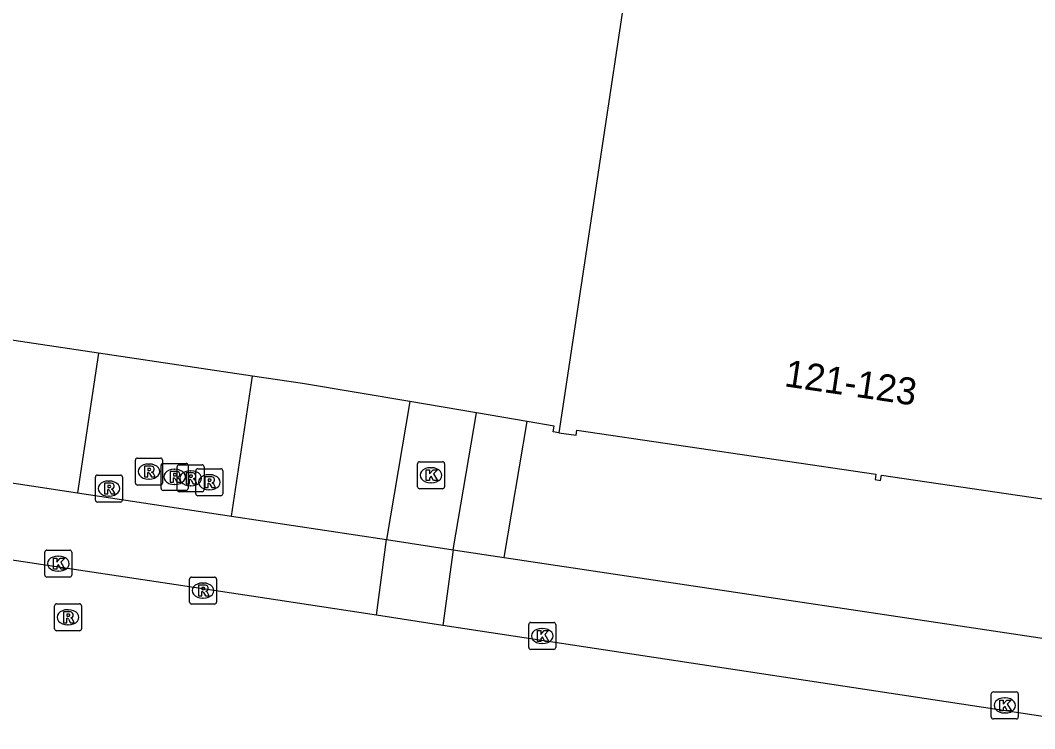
# Model space of a CAD drawing. Extents: x 163010 to 163853, y 382793 to 383982.
# Drawn here: x 163603.4 to 163641, y 382812.73 to 382838.98 of the extents above; entities that cross this region are included whole.
import ezdxf

# ---------------------------------------------------------------- set-up
doc = ezdxf.new("R2010")
doc.units = 0
for name, color, linetype in [('IMGEO_Kolk', 7, 'Continuous'), ('IMGEO_Pand', 7, 'Continuous'), ('IMGEO_Pand_nummerreeks', 7, 'Continuous'), ('IMGEO_Parkeervlak_open', 7, 'Continuous'), ('IMGEO_Rijbaan_lokaal_open', 7, 'Continuous'), ('IMGEO_Rioolput', 7, 'Continuous'), ('IMGEO_Voetpad_open', 7, 'Continuous')]:
    doc.layers.add(name, color=color, linetype=linetype)

msp = doc.modelspace()

# ---------------------------------------------------------------- linework, layer by layer
at = {"layer": 'IMGEO_Kolk'}
for p, q in [((163618.126, 382821.699), (163618.126, 382822.551)), ((163618.201, 382822.625), (163619.053, 382822.625)), ((163618.614, 382822.405), (163618.639, 382822.405)), ((163619.127, 382822.551), (163619.127, 382821.699)), ((163618.637, 382821.845), (163618.612, 382821.845)), ((163619.053, 382821.625), (163618.201, 382821.625)), ((163604.309, 382818.423), (163604.309, 382819.275)), ((163604.384, 382819.349), (163605.236, 382819.349)), ((163604.797, 382819.129), (163604.822, 382819.129)), ((163605.31, 382819.275), (163605.31, 382818.423)), ((163605.236, 382818.349), (163604.384, 382818.349)), ((163604.82, 382818.569), (163604.795, 382818.569)), ((163622.248, 382815.742), (163622.248, 382816.594)), ((163622.323, 382816.668), (163623.175, 382816.668)), ((163622.736, 382816.448), (163622.761, 382816.448)), ((163623.249, 382816.594), (163623.249, 382815.742)), ((163623.175, 382815.668), (163622.323, 382815.668)), ((163622.759, 382815.888), (163622.734, 382815.888)), ((163639.395, 382813.168), (163639.395, 382814.02)), ((163639.47, 382814.094), (163640.322, 382814.094)), ((163639.883, 382813.874), (163639.908, 382813.874)), ((163640.396, 382814.02), (163640.396, 382813.168)), ((163640.322, 382813.094), (163639.47, 382813.094)), ((163639.906, 382813.314), (163639.881, 382813.314))]:
    msp.add_line(p, q, dxfattribs=at)
for points in [[(163618.126, 382821.699), (163618.126, 382822.551)], [(163618.201, 382822.625), (163619.053, 382822.625)], [(163619.127, 382822.551), (163619.127, 382821.699)], [(163618.447, 382822.325), (163618.57, 382822.325), (163618.57, 382822.174), (163618.7, 382822.325), (163618.864, 382822.325), (163618.718, 382822.174), (163618.871, 382821.925), (163618.719, 382821.925), (163618.634, 382822.089), (163618.57, 382822.022), (163618.57, 382821.925), (163618.447, 382821.925), (163618.447, 382822.325)], [(163619.053, 382821.625), (163618.201, 382821.625)], [(163604.309, 382818.423), (163604.309, 382819.275)], [(163604.384, 382819.349), (163605.236, 382819.349)], [(163604.63, 382819.049), (163604.753, 382819.049), (163604.753, 382818.898), (163604.883, 382819.049), (163605.047, 382819.049), (163604.901, 382818.898), (163605.054, 382818.649), (163604.902, 382818.649), (163604.817, 382818.813), (163604.753, 382818.746), (163604.753, 382818.649), (163604.63, 382818.649), (163604.63, 382819.049)], [(163605.31, 382819.275), (163605.31, 382818.423)], [(163605.236, 382818.349), (163604.384, 382818.349)], [(163622.248, 382815.742), (163622.248, 382816.594)], [(163622.323, 382816.668), (163623.175, 382816.668)], [(163623.249, 382816.594), (163623.249, 382815.742)], [(163622.569, 382816.368), (163622.692, 382816.368), (163622.692, 382816.217), (163622.822, 382816.368), (163622.986, 382816.368), (163622.84, 382816.217), (163622.993, 382815.968), (163622.841, 382815.968), (163622.756, 382816.132), (163622.692, 382816.065), (163622.692, 382815.968), (163622.569, 382815.968), (163622.569, 382816.368)], [(163623.175, 382815.668), (163622.323, 382815.668)], [(163639.395, 382813.168), (163639.395, 382814.02)], [(163639.47, 382814.094), (163640.322, 382814.094)], [(163639.716, 382813.794), (163639.839, 382813.794), (163639.839, 382813.643), (163639.969, 382813.794), (163640.133, 382813.794), (163639.987, 382813.643), (163640.14, 382813.394), (163639.988, 382813.394), (163639.903, 382813.558), (163639.839, 382813.491), (163639.839, 382813.394), (163639.716, 382813.394), (163639.716, 382813.794)], [(163640.396, 382814.02), (163640.396, 382813.168)], [(163640.322, 382813.094), (163639.47, 382813.094)]]:
    msp.add_lwpolyline(points, dxfattribs=at)
for centre, start, end in [((163618.203, 382822.549), 91.552, 178.448), ((163618.203, 382822.549), 91.552, 178.448), ((163619.051, 382822.549), 1.552, 88.448), ((163619.051, 382822.549), 1.552, 88.448), ((163618.203, 382821.701), 181.552, 268.448), ((163618.203, 382821.701), 181.552, 268.448), ((163619.051, 382821.701), 271.552, 358.448), ((163619.051, 382821.701), 271.552, 358.448), ((163604.386, 382819.273), 91.552, 178.448), ((163604.386, 382819.273), 91.552, 178.448), ((163605.234, 382819.273), 1.552, 88.448), ((163605.234, 382819.273), 1.552, 88.448), ((163604.386, 382818.425), 181.552, 268.448), ((163604.386, 382818.425), 181.552, 268.448), ((163605.234, 382818.425), 271.552, 358.448), ((163605.234, 382818.425), 271.552, 358.448), ((163622.325, 382816.592), 91.552, 178.448), ((163622.325, 382816.592), 91.552, 178.448), ((163623.173, 382816.592), 1.552, 88.448), ((163623.173, 382816.592), 1.552, 88.448), ((163622.325, 382815.744), 181.552, 268.448), ((163622.325, 382815.744), 181.552, 268.448), ((163623.173, 382815.744), 271.552, 358.448), ((163623.173, 382815.744), 271.552, 358.448), ((163639.472, 382814.018), 91.552, 178.448), ((163639.472, 382814.018), 91.552, 178.448), ((163640.32, 382814.018), 1.552, 88.448), ((163640.32, 382814.018), 1.552, 88.448), ((163639.472, 382813.17), 181.552, 268.448), ((163639.472, 382813.17), 181.552, 268.448), ((163640.32, 382813.17), 271.552, 358.448), ((163640.32, 382813.17), 271.552, 358.448)]:
    msp.add_arc(centre, 0.0765, start, end, dxfattribs=at)
for centre, major_axis, ratio, start_param, end_param in [((163618.613, 382822.125), (-0.387, 0.002), 0.722429, 4.712389, 7.853982), ((163618.638, 382822.125), (-0.39, 0.002), 0.717154, 1.570796, 4.712389), ((163604.796, 382818.849), (-0.387, 0.002), 0.722429, 4.712389, 7.853982), ((163604.821, 382818.849), (-0.39, 0.002), 0.717154, 1.570796, 4.712389), ((163622.735, 382816.168), (-0.387, 0.002), 0.722429, 4.712389, 7.853982), ((163622.76, 382816.168), (-0.39, 0.002), 0.717154, 1.570796, 4.712389), ((163639.882, 382813.594), (-0.387, 0.002), 0.722429, 4.712389, 7.853982), ((163639.907, 382813.594), (-0.39, 0.002), 0.717154, 1.570796, 4.712389)]:
    msp.add_ellipse(centre, major_axis=major_axis, ratio=ratio, start_param=start_param, end_param=end_param, dxfattribs=at)
at = {"layer": 'IMGEO_Pand'}
for points in [[(163632.813, 382886.325), (163623.367, 382823.699)], [(163606.296, 382826.651), (163596.21, 382828.157)], [(163612.003, 382825.799), (163606.296, 382826.651)], [(163617.839, 382824.851), (163613.862, 382825.522), (163612.003, 382825.799)], [(163620.306, 382824.434), (163617.839, 382824.851)], [(163622.192, 382824.116), (163620.306, 382824.434)], [(163623.367, 382823.699), (163623.155, 382823.73), (163623.187, 382823.948), (163622.192, 382824.116)], [(163623.367, 382823.699), (163624.005, 382823.606), (163624.033, 382823.795), (163635.119, 382822.162), (163635.089, 382821.964), (163635.286, 382821.935), (163635.329, 382822.122), (163645.496, 382820.628)]]:
    msp.add_lwpolyline(points, dxfattribs=at)
at = {"layer": 'IMGEO_Parkeervlak_open'}
msp.add_lwpolyline([(163621.341, 382819.074), (163622.192, 382824.116)], dxfattribs=at)
at = {"layer": 'IMGEO_Rijbaan_lokaal_open'}
for points in [[(163616.599, 382816.941), (163611.973, 382817.64), (163603.009, 382818.995), (163595.965, 382820.06), (163595.022, 382820.202)], [(163619.059, 382816.555), (163616.599, 382816.941)], [(163644.324, 382812.732), (163619.059, 382816.555)]]:
    msp.add_lwpolyline(points, dxfattribs=at)
at = {"layer": 'IMGEO_Rioolput'}
for p, q in [((163607.669, 382821.835), (163607.669, 382822.687)), ((163607.744, 382822.761), (163608.596, 382822.761)), ((163608.157, 382822.541), (163608.182, 382822.541)), ((163608.62, 382821.638), (163608.62, 382822.49)), ((163608.67, 382822.687), (163608.67, 382821.835)), ((163608.695, 382822.564), (163609.547, 382822.564)), ((163609.215, 382821.585), (163609.215, 382822.437)), ((163609.29, 382822.511), (163610.142, 382822.511)), ((163609.621, 382822.49), (163609.621, 382821.638)), ((163610.216, 382822.437), (163610.216, 382821.585)), ((163606.185, 382821.205), (163606.185, 382822.057)), ((163606.26, 382822.131), (163607.112, 382822.131)), ((163607.186, 382822.057), (163607.186, 382821.205)), ((163609.108, 382822.344), (163609.133, 382822.344)), ((163609.703, 382822.291), (163609.728, 382822.291)), ((163609.907, 382821.44), (163609.907, 382822.292)), ((163609.982, 382822.366), (163610.834, 382822.366)), ((163610.395, 382822.146), (163610.42, 382822.146)), ((163610.908, 382822.292), (163610.908, 382821.44)), ((163606.673, 382821.911), (163606.698, 382821.911)), ((163608.596, 382821.761), (163607.744, 382821.761)), ((163608.18, 382821.981), (163608.155, 382821.981)), ((163609.131, 382821.784), (163609.106, 382821.784)), ((163609.726, 382821.731), (163609.701, 382821.731)), ((163606.696, 382821.351), (163606.671, 382821.351)), ((163609.547, 382821.564), (163608.695, 382821.564)), ((163610.142, 382821.511), (163609.29, 382821.511)), ((163610.834, 382821.366), (163609.982, 382821.366)), ((163610.418, 382821.586), (163610.393, 382821.586)), ((163607.112, 382821.131), (163606.26, 382821.131)), ((163609.674, 382817.424), (163609.674, 382818.276)), ((163609.749, 382818.35), (163610.601, 382818.35)), ((163610.675, 382818.276), (163610.675, 382817.424)), ((163610.162, 382818.13), (163610.187, 382818.13)), ((163610.185, 382817.57), (163610.16, 382817.57)), ((163604.67, 382816.435), (163604.67, 382817.287)), ((163604.745, 382817.361), (163605.597, 382817.361)), ((163605.158, 382817.141), (163605.183, 382817.141)), ((163605.671, 382817.287), (163605.671, 382816.435)), ((163610.601, 382817.35), (163609.749, 382817.35)), ((163605.181, 382816.581), (163605.156, 382816.581)), ((163605.597, 382816.361), (163604.745, 382816.361))]:
    msp.add_line(p, q, dxfattribs=at)
for points in [[(163607.669, 382821.835), (163607.669, 382822.687)], [(163607.744, 382822.761), (163608.596, 382822.761)], [(163608.258, 382822.459), (163608.006, 382822.461), (163608.006, 382822.061)], [(163608.62, 382821.638), (163608.62, 382822.49)], [(163608.67, 382822.687), (163608.67, 382821.835)], [(163608.695, 382822.564), (163609.547, 382822.564)], [(163609.215, 382821.585), (163609.215, 382822.437)], [(163609.29, 382822.511), (163610.142, 382822.511)], [(163609.621, 382822.49), (163609.621, 382821.638)], [(163610.216, 382822.437), (163610.216, 382821.585)], [(163606.185, 382821.205), (163606.185, 382822.057)], [(163606.26, 382822.131), (163607.112, 382822.131)], [(163607.186, 382822.057), (163607.186, 382821.205)], [(163608.006, 382822.061), (163608.13, 382822.061), (163608.13, 382822.223), (163608.141, 382822.223)], [(163608.184, 382822.38), (163608.13, 382822.38), (163608.13, 382822.299)], [(163608.13, 382822.299), (163608.182, 382822.299)], [(163608.188, 382822.194), (163608.259, 382822.061), (163608.399, 382822.061), (163608.334, 382822.187)], [(163609.209, 382822.262), (163608.957, 382822.264), (163608.957, 382821.864)], [(163609.135, 382822.183), (163609.081, 382822.183), (163609.081, 382822.102)], [(163609.081, 382822.102), (163609.133, 382822.102)], [(163609.804, 382822.209), (163609.552, 382822.211), (163609.552, 382821.811)], [(163609.73, 382822.13), (163609.676, 382822.13), (163609.676, 382822.049)], [(163609.676, 382822.049), (163609.728, 382822.049)], [(163609.907, 382821.44), (163609.907, 382822.292)], [(163609.982, 382822.366), (163610.834, 382822.366)], [(163610.496, 382822.064), (163610.244, 382822.066), (163610.244, 382821.666)], [(163610.908, 382822.292), (163610.908, 382821.44)], [(163606.774, 382821.829), (163606.522, 382821.831), (163606.522, 382821.431)], [(163606.7, 382821.75), (163606.646, 382821.75), (163606.646, 382821.669)], [(163606.646, 382821.669), (163606.698, 382821.669)], [(163608.596, 382821.761), (163607.744, 382821.761)], [(163608.957, 382821.864), (163609.081, 382821.864), (163609.081, 382822.026), (163609.092, 382822.026)], [(163609.139, 382821.997), (163609.21, 382821.864), (163609.35, 382821.864), (163609.285, 382821.99)], [(163609.552, 382821.811), (163609.676, 382821.811), (163609.676, 382821.973), (163609.687, 382821.973)], [(163609.734, 382821.944), (163609.805, 382821.811), (163609.945, 382821.811), (163609.88, 382821.937)], [(163610.244, 382821.666), (163610.368, 382821.666), (163610.368, 382821.828), (163610.379, 382821.828)], [(163610.422, 382821.985), (163610.368, 382821.985), (163610.368, 382821.904)], [(163610.368, 382821.904), (163610.42, 382821.904)], [(163610.426, 382821.799), (163610.497, 382821.666), (163610.637, 382821.666), (163610.572, 382821.792)], [(163606.522, 382821.431), (163606.646, 382821.431), (163606.646, 382821.593), (163606.657, 382821.593)], [(163606.704, 382821.564), (163606.775, 382821.431), (163606.915, 382821.431), (163606.85, 382821.557)], [(163609.547, 382821.564), (163608.695, 382821.564)], [(163610.142, 382821.511), (163609.29, 382821.511)], [(163610.834, 382821.366), (163609.982, 382821.366)], [(163607.112, 382821.131), (163606.26, 382821.131)], [(163609.674, 382817.424), (163609.674, 382818.276)], [(163609.749, 382818.35), (163610.601, 382818.35)], [(163610.675, 382818.276), (163610.675, 382817.424)], [(163610.263, 382818.048), (163610.011, 382818.05), (163610.011, 382817.65)], [(163610.189, 382817.969), (163610.135, 382817.969), (163610.135, 382817.888)], [(163610.011, 382817.65), (163610.135, 382817.65), (163610.135, 382817.812), (163610.146, 382817.812)], [(163610.135, 382817.888), (163610.187, 382817.888)], [(163610.193, 382817.783), (163610.264, 382817.65), (163610.404, 382817.65), (163610.339, 382817.776)], [(163604.67, 382816.435), (163604.67, 382817.287)], [(163604.745, 382817.361), (163605.597, 382817.361)], [(163605.671, 382817.287), (163605.671, 382816.435)], [(163610.601, 382817.35), (163609.749, 382817.35)], [(163605.259, 382817.059), (163605.007, 382817.061), (163605.007, 382816.661)], [(163605.007, 382816.661), (163605.131, 382816.661), (163605.131, 382816.823), (163605.142, 382816.823)], [(163605.185, 382816.98), (163605.131, 382816.98), (163605.131, 382816.899)], [(163605.131, 382816.899), (163605.183, 382816.899)], [(163605.189, 382816.794), (163605.26, 382816.661), (163605.4, 382816.661), (163605.335, 382816.787)], [(163605.597, 382816.361), (163604.745, 382816.361)]]:
    msp.add_lwpolyline(points, dxfattribs=at)
for centre, radius, start, end in [((163607.746, 382822.685), 0.0765, 91.552, 178.448), ((163607.746, 382822.685), 0.0765, 91.552, 178.448), ((163608.257, 382822.349), 0.109, 350.3612, 89.416), ((163608.594, 382822.685), 0.0765, 1.552, 88.448), ((163608.594, 382822.685), 0.0765, 1.552, 88.448), ((163608.697, 382822.488), 0.0765, 91.552, 178.448), ((163608.697, 382822.488), 0.0765, 91.552, 178.448), ((163609.292, 382822.435), 0.0765, 91.552, 178.448), ((163609.292, 382822.435), 0.0765, 91.552, 178.448), ((163609.545, 382822.488), 0.0765, 1.552, 88.448), ((163609.545, 382822.488), 0.0765, 1.552, 88.448), ((163610.14, 382822.435), 0.0765, 1.552, 88.448), ((163610.14, 382822.435), 0.0765, 1.552, 88.448), ((163606.262, 382822.055), 0.0765, 91.552, 178.448), ((163606.262, 382822.055), 0.0765, 91.552, 178.448), ((163607.11, 382822.055), 0.0765, 1.552, 88.448), ((163607.11, 382822.055), 0.0765, 1.552, 88.448), ((163608.14, 382822.17), 0.0533, 26.0293, 88.6989), ((163608.166, 382822.488), 0.19, 274.7715, 282.9687), ((163608.19, 382822.284), 0.0964, 77.0061, 93.1865), ((163608.204, 382822.341), 0.0378, 276.6634, 79.6772), ((163608.255, 382822.349), 0.112, 277.5842, 350.9817), ((163608.239, 382822.134), 0.108, 29.5134, 73.7905), ((163609.117, 382822.291), 0.19, 274.7715, 282.9687), ((163609.141, 382822.087), 0.0964, 77.0061, 93.1865), ((163609.155, 382822.144), 0.0378, 276.6634, 79.6772), ((163609.208, 382822.152), 0.109, 350.3612, 89.416), ((163609.206, 382822.152), 0.112, 277.5842, 350.9817), ((163609.19, 382821.937), 0.108, 29.5134, 73.7905), ((163609.712, 382822.238), 0.19, 274.7715, 282.9687), ((163609.736, 382822.034), 0.0964, 77.0061, 93.1865), ((163609.75, 382822.091), 0.0378, 276.6634, 79.6772), ((163609.803, 382822.099), 0.109, 350.3612, 89.416), ((163609.801, 382822.099), 0.112, 277.5842, 350.9817), ((163609.984, 382822.29), 0.0765, 91.552, 178.448), ((163609.984, 382822.29), 0.0765, 91.552, 178.448), ((163610.495, 382821.954), 0.109, 350.3612, 89.416), ((163610.832, 382822.29), 0.0765, 1.552, 88.448), ((163610.832, 382822.29), 0.0765, 1.552, 88.448), ((163606.682, 382821.858), 0.19, 274.7715, 282.9687), ((163606.706, 382821.654), 0.0964, 77.0061, 93.1865), ((163606.72, 382821.711), 0.0378, 276.6634, 79.6772), ((163606.773, 382821.719), 0.109, 350.3612, 89.416), ((163606.771, 382821.719), 0.112, 277.5842, 350.9817), ((163607.746, 382821.837), 0.0765, 181.552, 268.448), ((163607.746, 382821.837), 0.0765, 181.552, 268.448), ((163608.594, 382821.837), 0.0765, 271.552, 358.448), ((163608.594, 382821.837), 0.0765, 271.552, 358.448), ((163609.091, 382821.973), 0.0533, 26.0293, 88.6989), ((163609.686, 382821.92), 0.0533, 26.0293, 88.6989), ((163609.785, 382821.884), 0.108, 29.5134, 73.7905), ((163610.378, 382821.775), 0.0533, 26.0293, 88.6989), ((163610.404, 382822.093), 0.19, 274.7715, 282.9687), ((163610.428, 382821.889), 0.0964, 77.0061, 93.1865), ((163610.442, 382821.946), 0.0378, 276.6634, 79.6772), ((163610.493, 382821.954), 0.112, 277.5842, 350.9817), ((163610.477, 382821.739), 0.108, 29.5134, 73.7905), ((163606.656, 382821.54), 0.0533, 26.0293, 88.6989), ((163606.755, 382821.504), 0.108, 29.5134, 73.7905), ((163608.697, 382821.64), 0.0765, 181.552, 268.448), ((163608.697, 382821.64), 0.0765, 181.552, 268.448), ((163609.292, 382821.587), 0.0765, 181.552, 268.448), ((163609.292, 382821.587), 0.0765, 181.552, 268.448), ((163609.545, 382821.64), 0.0765, 271.552, 358.448), ((163609.545, 382821.64), 0.0765, 271.552, 358.448), ((163609.984, 382821.442), 0.0765, 181.552, 268.448), ((163609.984, 382821.442), 0.0765, 181.552, 268.448), ((163610.14, 382821.587), 0.0765, 271.552, 358.448), ((163610.14, 382821.587), 0.0765, 271.552, 358.448), ((163610.832, 382821.442), 0.0765, 271.552, 358.448), ((163610.832, 382821.442), 0.0765, 271.552, 358.448), ((163606.262, 382821.207), 0.0765, 181.552, 268.448), ((163606.262, 382821.207), 0.0765, 181.552, 268.448), ((163607.11, 382821.207), 0.0765, 271.552, 358.448), ((163607.11, 382821.207), 0.0765, 271.552, 358.448), ((163609.751, 382818.274), 0.0765, 91.552, 178.448), ((163609.751, 382818.274), 0.0765, 91.552, 178.448), ((163610.599, 382818.274), 0.0765, 1.552, 88.448), ((163610.599, 382818.274), 0.0765, 1.552, 88.448), ((163610.171, 382818.077), 0.19, 274.7715, 282.9687), ((163610.195, 382817.873), 0.0964, 77.0061, 93.1865), ((163610.209, 382817.93), 0.0378, 276.6634, 79.6772), ((163610.262, 382817.938), 0.109, 350.3612, 89.416), ((163610.26, 382817.938), 0.112, 277.5842, 350.9817), ((163610.145, 382817.759), 0.0533, 26.0293, 88.6989), ((163610.244, 382817.723), 0.108, 29.5134, 73.7905), ((163604.747, 382817.285), 0.0765, 91.552, 178.448), ((163604.747, 382817.285), 0.0765, 91.552, 178.448), ((163605.595, 382817.285), 0.0765, 1.552, 88.448), ((163605.595, 382817.285), 0.0765, 1.552, 88.448), ((163609.751, 382817.426), 0.0765, 181.552, 268.448), ((163609.751, 382817.426), 0.0765, 181.552, 268.448), ((163610.599, 382817.426), 0.0765, 271.552, 358.448), ((163610.599, 382817.426), 0.0765, 271.552, 358.448), ((163605.141, 382816.77), 0.0533, 26.0293, 88.6989), ((163605.167, 382817.088), 0.19, 274.7715, 282.9687), ((163605.191, 382816.884), 0.0964, 77.0061, 93.1865), ((163605.205, 382816.941), 0.0378, 276.6634, 79.6772), ((163605.258, 382816.949), 0.109, 350.3612, 89.416), ((163605.256, 382816.949), 0.112, 277.5842, 350.9817), ((163605.24, 382816.734), 0.108, 29.5134, 73.7905), ((163604.747, 382816.437), 0.0765, 181.552, 268.448), ((163604.747, 382816.437), 0.0765, 181.552, 268.448), ((163605.595, 382816.437), 0.0765, 271.552, 358.448), ((163605.595, 382816.437), 0.0765, 271.552, 358.448)]:
    msp.add_arc(centre, radius, start, end, dxfattribs=at)
for centre, major_axis, ratio, start_param, end_param in [((163608.156, 382822.261), (-0.387, 0.002), 0.722429, 4.712389, 7.853982), ((163608.181, 382822.261), (-0.39, 0.002), 0.717154, 1.570796, 4.712389), ((163609.107, 382822.064), (-0.387, 0.002), 0.722429, 4.712389, 7.853982), ((163609.132, 382822.064), (-0.39, 0.002), 0.717154, 1.570796, 4.712389), ((163609.702, 382822.011), (-0.387, 0.002), 0.722429, 4.712389, 7.853982), ((163609.727, 382822.011), (-0.39, 0.002), 0.717154, 1.570796, 4.712389), ((163610.394, 382821.866), (-0.387, 0.002), 0.722429, 4.712389, 7.853982), ((163610.419, 382821.866), (-0.39, 0.002), 0.717154, 1.570796, 4.712389), ((163606.672, 382821.631), (-0.387, 0.002), 0.722429, 4.712389, 7.853982), ((163606.697, 382821.631), (-0.39, 0.002), 0.717154, 1.570796, 4.712389), ((163610.161, 382817.85), (-0.387, 0.002), 0.722429, 4.712389, 7.853982), ((163610.186, 382817.85), (-0.39, 0.002), 0.717154, 1.570796, 4.712389), ((163605.157, 382816.861), (-0.387, 0.002), 0.722429, 4.712389, 7.853982), ((163605.182, 382816.861), (-0.39, 0.002), 0.717154, 1.570796, 4.712389)]:
    msp.add_ellipse(centre, major_axis=major_axis, ratio=ratio, start_param=start_param, end_param=end_param, dxfattribs=at)
at = {"layer": 'IMGEO_Voetpad_open'}
for points in [[(163606.296, 382826.651), (163605.524, 382821.475)], [(163611.228, 382820.611), (163612.003, 382825.799)], [(163617.839, 382824.851), (163616.976, 382819.74)], [(163619.449, 382819.357), (163620.306, 382824.434)], [(163595.44, 382823.002), (163605.524, 382821.475)], [(163605.524, 382821.475), (163611.228, 382820.611)], [(163611.228, 382820.611), (163616.976, 382819.74)], [(163616.599, 382816.941), (163616.976, 382819.74)], [(163616.976, 382819.74), (163619.449, 382819.357)], [(163619.449, 382819.357), (163619.059, 382816.555)], [(163619.449, 382819.357), (163621.341, 382819.074)], [(163621.341, 382819.074), (163644.746, 382815.572)]]:
    msp.add_lwpolyline(points, dxfattribs=at)

# ---------------------------------------------------------------- texts
at = {"layer": 'IMGEO_Pand_nummerreeks'}
msp.add_text('121-123', height=1, rotation=351.5317, dxfattribs=at).set_placement((163631.691, 382825.426))

doc.saveas('drawing.dxf')
